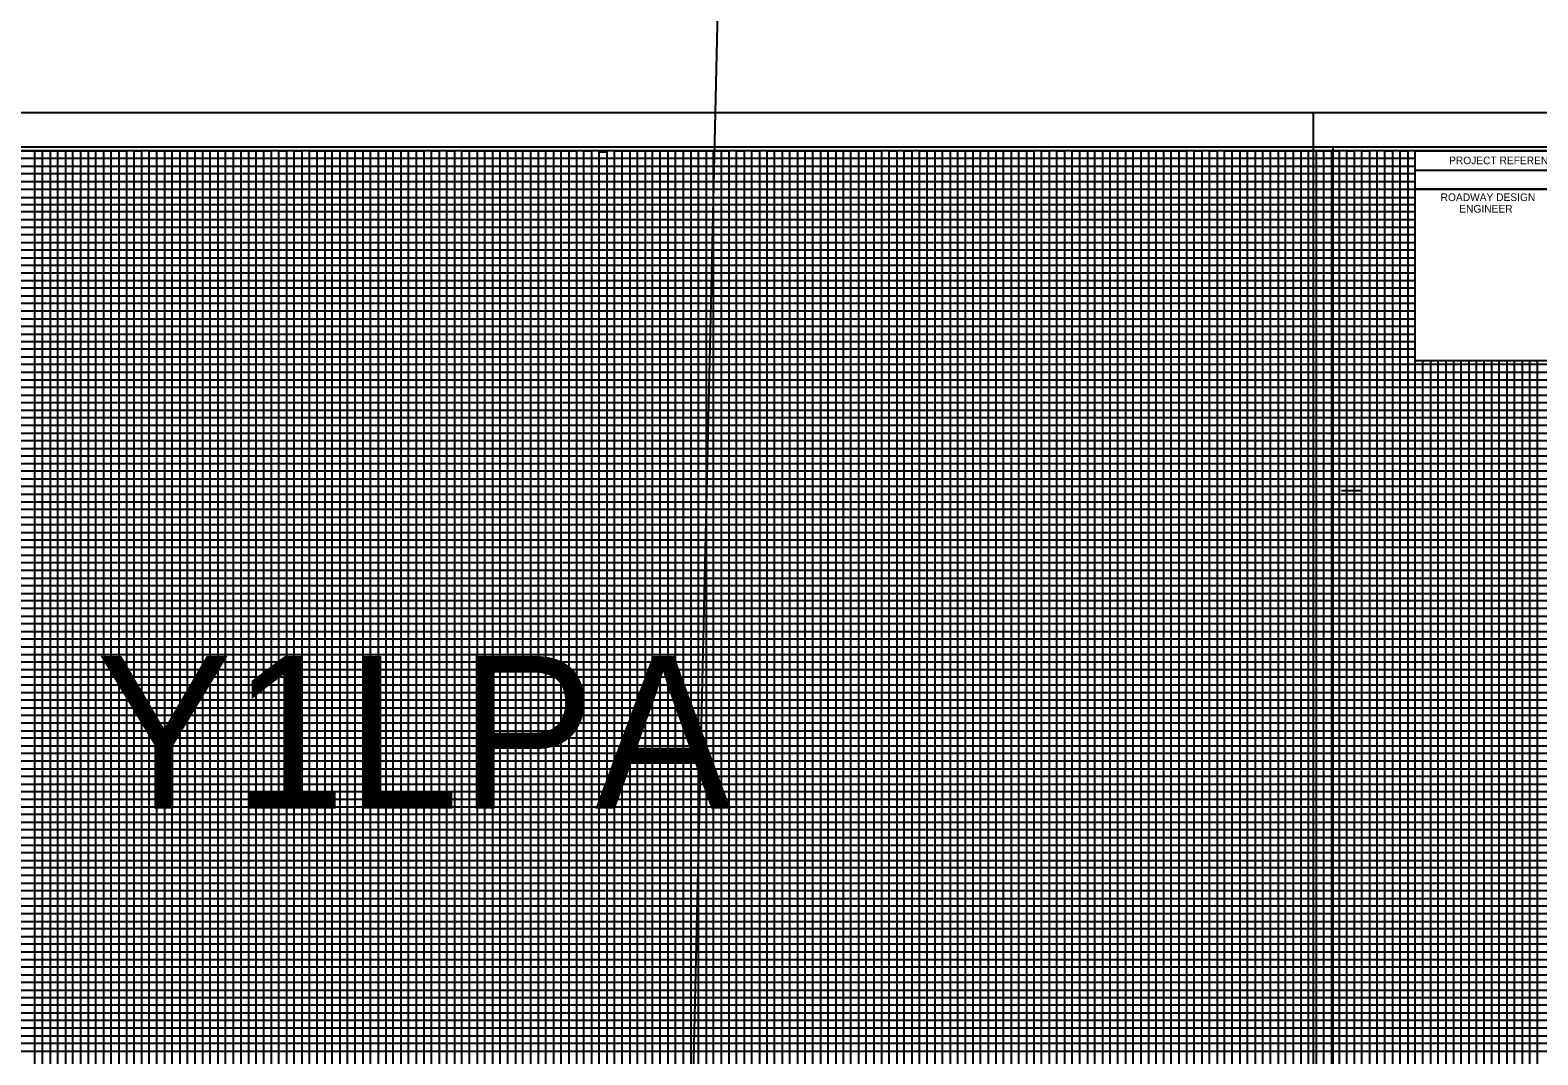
# Model space of a CAD drawing. Extents: x 2345490 to 2436403, y 465165 to 573888.
# Drawn here: x 2411237 to 2412226, y 518915 to 519587 of the extents above; entities that cross this region are included whole.
import ezdxf

# ---------------------------------------------------------------- set-up
doc = ezdxf.new("R2010")
doc.units = 0
for name, color, linetype in [('Old_Level_18', 7, 'Continuous'), ('Old_Level_2', 7, 'Continuous'), ('Old_Level_3', 7, 'Continuous'), ('Old_Level_40', 7, 'Continuous'), ('Old_Level_41', 7, 'Continuous'), ('Old_Level_42', 7, 'Continuous'), ('Old_Level_43', 7, 'Continuous'), ('Old_Level_44', 7, 'Continuous'), ('Old_Level_50', 7, 'Continuous'), ('Old_Level_51', 7, 'Continuous')]:
    doc.layers.add(name, color=color, linetype=linetype)

msp = doc.modelspace()

# ---------------------------------------------------------------- linework, layer by layer
at = {"layer": 'Old_Level_18'}
msp.add_lwpolyline([(2412345.325, 519507.40475), (2410845.325, 519507.40475), (2410845.325, 518457.40475), (2412345.325, 518457.40475)], close=True, dxfattribs=at)
at = {"layer": 'Old_Level_2'}
msp.add_line((2411722.59175, 521117.51825), (2411239.1575, 499960.77), dxfattribs=at)
at = {"layer": 'Old_Level_40'}
msp.add_line((2412145.275, 519494.85475), (2412345.325, 519494.85475), dxfattribs=at)
for points in [[(2412145.275, 519507.40475), (2412345.325, 519507.40475), (2412345.325, 519482.35475), (2412145.275, 519482.35475)], [(2412145.275, 519482.35475), (2412245.325, 519482.35475), (2412245.325, 519369.85475), (2412145.275, 519369.85475)]]:
    msp.add_lwpolyline(points, close=True, dxfattribs=at)
at = {"layer": 'Old_Level_41'}
msp.add_line((2412096.825, 519284.90475), (2412109.325, 519284.90475), dxfattribs=at)
for points in [[(2411220.325, 519507.40475), (2411270.325, 519507.40475), (2411270.325, 518482.40475)], [(2411245.325, 518482.40475), (2411245.325, 519507.40475), (2411295.325, 519507.40475), (2411295.325, 518482.40475)], [(2411320.325, 518482.40475), (2411320.325, 519507.40475), (2411370.325, 519507.40475), (2411370.325, 518482.40475)], [(2411345.325, 518482.40475), (2411345.325, 519507.40475), (2411395.325, 519507.40475), (2411395.325, 518482.40475)], [(2411420.325, 518482.40475), (2411420.325, 519507.40475), (2411470.325, 519507.40475), (2411470.325, 518482.40475)], [(2411445.325, 518482.40475), (2411445.325, 519507.40475), (2411495.325, 519507.40475), (2411495.325, 518482.40475)], [(2411520.325, 518482.40475), (2411520.325, 519507.40475), (2411570.325, 519507.40475), (2411570.325, 518482.40475)], [(2411545.325, 518482.40475), (2411545.325, 519507.40475), (2411595.325, 519507.40475), (2411595.325, 518482.40475)], [(2411620.325, 518482.40475), (2411620.325, 519507.40475), (2411670.325, 519507.40475), (2411670.325, 518482.40475)], [(2411645.325, 518482.40475), (2411645.325, 519507.40475), (2411695.325, 519507.40475), (2411695.325, 518482.40475)], [(2411720.325, 518482.40475), (2411720.325, 519507.40475), (2411770.325, 519507.40475), (2411770.325, 518482.40475)], [(2411745.325, 518482.40475), (2411745.325, 519507.40475), (2411795.325, 519507.40475), (2411795.325, 518482.40475)], [(2411820.325, 518482.40475), (2411820.325, 519507.40475), (2411870.325, 519507.40475), (2411870.325, 518482.40475)], [(2411845.325, 518482.40475), (2411845.325, 519507.40475), (2411895.325, 519507.40475), (2411895.325, 518482.40475)], [(2411920.325, 518482.40475), (2411920.325, 519507.40475), (2411970.325, 519507.40475), (2411970.325, 518482.40475)], [(2411945.325, 518482.40475), (2411945.325, 519507.40475), (2411995.325, 519507.40475), (2411995.325, 518482.40475)], [(2412020.325, 518482.40475), (2412020.325, 519507.40475), (2412070.325, 519507.40475), (2412070.325, 518482.40475)], [(2412045.325, 518482.40475), (2412045.325, 519507.40475), (2412095.325, 519507.40475), (2412095.325, 518482.40475)], [(2412120.325, 518482.40475), (2412120.325, 519507.40475)], [(2412145.325, 518482.40475), (2412145.325, 519507.40475), (2412171.625, 519507.40475)], [(2410845.325, 519457.40475), (2412145.275, 519457.40475)], [(2412145.275, 519407.40475), (2410845.325, 519407.40475), (2410845.325, 519357.35475), (2412345.325, 519357.35475)], [(2412345.325, 519332.40475), (2410845.325, 519332.40475), (2410845.325, 519382.40475), (2412145.275, 519382.40475)], [(2412170.325, 519369.85475), (2412170.325, 518482.40475), (2412220.325, 518482.40475), (2412220.325, 519369.85475)], [(2412345.325, 519307.40475), (2410845.325, 519307.40475), (2410845.325, 519257.40475), (2412345.325, 519257.40475)], [(2412345.325, 519232.40475), (2410845.325, 519232.40475), (2410845.325, 519282.40475), (2412345.325, 519282.40475)], [(2412345.325, 519207.40475), (2410845.325, 519207.40475), (2410845.325, 519157.40475), (2412345.325, 519157.40475)], [(2412345.325, 519107.40475), (2410845.325, 519107.40475), (2410845.325, 519057.40475), (2412345.325, 519057.40475)], [(2412345.325, 519007.40475), (2410845.325, 519007.40475), (2410845.325, 518957.40475), (2412345.325, 518957.40475)]]:
    msp.add_lwpolyline(points, dxfattribs=at)
at = {"layer": 'Old_Level_42'}
for points in [[(2412145.275, 519432.40475), (2410845.425, 519432.40475), (2410845.425, 519482.35475), (2412145.275, 519482.35475)], [(2412195.325, 519369.85475), (2412195.325, 518482.40475), (2412245.325, 518482.40475), (2412245.325, 519369.85475)], [(2412345.325, 519132.40475), (2410845.325, 519132.40475), (2410845.325, 519182.40475), (2412345.325, 519182.40475)], [(2412345.325, 519032.40475), (2410845.325, 519032.40475), (2410845.325, 519082.40475), (2412345.325, 519082.40475)], [(2412345.325, 518932.40475), (2410845.325, 518932.40475), (2410845.325, 518982.40475), (2412345.325, 518982.40475)]]:
    msp.add_lwpolyline(points, dxfattribs=at)
at = {"layer": 'Old_Level_43'}
for p, q in [((2412295.325, 519327.40475), (2410895.325, 519327.40475)), ((2410895.325, 519322.40475), (2412295.325, 519322.40475)), ((2412295.325, 519302.40475), (2410895.325, 519302.40475))]:
    msp.add_line(p, q, dxfattribs=at)
for points in [[(2412145.275, 519502.40475), (2410895.325, 519502.40475), (2410895.325, 519497.40475), (2412145.275, 519497.40475)], [(2411240.325, 518482.40475), (2411240.325, 519507.40475), (2411250.325, 519507.40475), (2411250.325, 518482.40475)], [(2411255.325, 518482.40475), (2411255.325, 519507.40475), (2411260.325, 519507.40475), (2411260.325, 518482.40475)], [(2411265.325, 518482.40475), (2411265.325, 519507.40475), (2411275.325, 519507.40475), (2411275.325, 518482.40475)], [(2411280.325, 518482.40475), (2411280.325, 519507.40475), (2411285.325, 519507.40475), (2411285.325, 518482.40475)], [(2411290.325, 518482.40475), (2411290.325, 519507.40475), (2411300.325, 519507.40475), (2411300.325, 518482.40475)], [(2411305.325, 518482.40475), (2411305.325, 519507.40475), (2411310.325, 519507.40475), (2411310.325, 518482.40475)], [(2411315.325, 518482.40475), (2411315.325, 519507.40475), (2411325.325, 519507.40475), (2411325.325, 518482.40475)], [(2411330.325, 518482.40475), (2411330.325, 519507.40475), (2411335.325, 519507.40475), (2411335.325, 518482.40475)], [(2411340.325, 518482.40475), (2411340.325, 519507.40475), (2411350.325, 519507.40475), (2411350.325, 518482.40475)], [(2411355.325, 518482.40475), (2411355.325, 519507.40475), (2411360.325, 519507.40475), (2411360.325, 518482.40475)], [(2411365.325, 518482.40475), (2411365.325, 519507.40475), (2411375.325, 519507.40475), (2411375.325, 518482.40475)], [(2411380.325, 519507.40475), (2411380.325, 518482.40475), (2411385.325, 518482.40475), (2411385.325, 519507.40475), (2411390.325, 519507.40475), (2411390.325, 518482.40475), (2411400.325, 518482.40475), (2411400.325, 519507.40475), (2411405.325, 519507.40475), (2411405.325, 518482.40475), (2411410.325, 518482.40475), (2411410.325, 519507.40475), (2411415.325, 519507.40475), (2411415.325, 518482.40475)], [(2411425.325, 518482.40475), (2411425.325, 519507.40475), (2411430.325, 519507.40475), (2411430.325, 518482.40475)], [(2411435.325, 518482.40475), (2411435.325, 519507.40475), (2411440.325, 519507.40475), (2411440.325, 518482.40475)], [(2411450.325, 518482.40475), (2411450.325, 519507.40475), (2411455.325, 519507.40475), (2411455.325, 518482.40475)], [(2411460.325, 518482.40475), (2411460.325, 519507.40475), (2411465.325, 519507.40475), (2411465.325, 518482.40475)], [(2411475.325, 518482.40475), (2411475.325, 519507.40475), (2411480.325, 519507.40475), (2411480.325, 518482.40475)], [(2411485.325, 518482.40475), (2411485.325, 519507.40475), (2411490.325, 519507.40475), (2411490.325, 518482.40475)], [(2411500.325, 518482.40475), (2411500.325, 519507.40475), (2411505.325, 519507.40475), (2411505.325, 518482.40475)], [(2411510.325, 518482.40475), (2411510.325, 519507.40475), (2411515.325, 519507.40475), (2411515.325, 518482.40475)], [(2411525.325, 518482.40475), (2411525.325, 519507.40475), (2411530.325, 519507.40475), (2411530.325, 518482.40475)], [(2411535.325, 518482.40475), (2411535.325, 519507.40475), (2411540.325, 519507.40475), (2411540.325, 518482.40475)], [(2411550.325, 518482.40475), (2411550.325, 519507.40475), (2411555.325, 519507.40475), (2411555.325, 518482.40475)], [(2411560.325, 518482.40475), (2411560.325, 519507.40475), (2411565.325, 519507.40475), (2411565.325, 518482.40475)], [(2411575.325, 518482.40475), (2411575.325, 519507.40475), (2411580.325, 519507.40475), (2411580.325, 518482.40475)], [(2411585.325, 518482.40475), (2411585.325, 519507.40475), (2411590.325, 519507.40475), (2411590.325, 518482.40475)], [(2411600.325, 518482.40475), (2411600.325, 519507.40475), (2411605.325, 519507.40475), (2411605.325, 518482.40475)], [(2411610.325, 518482.40475), (2411610.325, 519506.80475), (2411615.325, 519506.80475), (2411615.325, 518482.40475)], [(2411625.325, 518482.40475), (2411625.325, 519507.40475), (2411630.325, 519507.40475), (2411630.325, 518482.40475)], [(2411635.325, 518482.40475), (2411635.325, 519507.40475), (2411640.325, 519507.40475), (2411640.325, 518482.40475)], [(2411650.325, 518482.40475), (2411650.325, 519507.40475), (2411655.325, 519507.40475), (2411655.325, 518482.40475)], [(2411660.325, 518482.40475), (2411660.325, 519507.40475), (2411665.325, 519507.40475), (2411665.325, 518482.40475)], [(2411675.325, 518482.40475), (2411675.325, 519507.40475), (2411680.325, 519507.40475), (2411680.325, 518482.40475)], [(2411685.325, 518482.40475), (2411685.325, 519507.40475), (2411690.325, 519507.40475), (2411690.325, 518482.40475)], [(2411700.325, 518482.40475), (2411700.325, 519507.40475), (2411705.325, 519507.40475), (2411705.325, 518482.40475)], [(2411710.325, 518482.40475), (2411710.325, 519507.40475), (2411715.325, 519507.40475), (2411715.325, 518482.40475)], [(2411725.325, 518482.40475), (2411725.325, 519507.40475), (2411730.325, 519507.40475), (2411730.325, 518482.40475)], [(2411735.325, 518482.40475), (2411735.325, 519507.40475), (2411740.325, 519507.40475), (2411740.325, 518482.40475)], [(2411750.325, 518482.40475), (2411750.325, 519507.40475), (2411755.325, 519507.40475), (2411755.325, 518482.40475)], [(2411760.325, 518482.40475), (2411760.325, 519507.40475), (2411765.325, 519507.40475), (2411765.325, 518482.40475)], [(2411775.325, 518482.40475), (2411775.325, 519507.40475), (2411780.325, 519507.40475), (2411780.325, 518482.40475)], [(2411785.325, 518482.40475), (2411785.325, 519507.40475), (2411790.325, 519507.40475), (2411790.325, 518482.40475)], [(2411800.325, 518482.40475), (2411800.325, 519507.40475), (2411805.325, 519507.40475), (2411805.325, 518482.40475)], [(2411810.325, 518482.40475), (2411810.325, 519507.40475), (2411815.325, 519507.40475), (2411815.325, 518482.40475)], [(2411825.325, 518482.40475), (2411825.325, 519507.40475), (2411830.325, 519507.40475), (2411830.325, 518482.40475)], [(2411835.325, 518482.40475), (2411835.325, 519507.40475), (2411840.325, 519507.40475), (2411840.325, 518482.40475)], [(2411850.325, 518482.40475), (2411850.325, 519507.40475), (2411855.325, 519507.40475), (2411855.325, 518482.40475)], [(2411860.325, 518482.40475), (2411860.325, 519507.40475), (2411865.325, 519507.40475), (2411865.325, 518482.40475)], [(2411875.325, 518482.40475), (2411875.325, 519507.40475), (2411880.325, 519507.40475), (2411880.325, 518482.40475)], [(2411885.325, 518482.40475), (2411885.325, 519507.40475), (2411890.325, 519507.40475), (2411890.325, 518482.40475)], [(2411900.325, 518482.40475), (2411900.325, 519507.40475), (2411905.325, 519507.40475), (2411905.325, 518482.40475)], [(2411910.325, 518482.40475), (2411910.325, 519507.40475), (2411915.325, 519507.40475), (2411915.325, 518482.40475)], [(2411925.325, 518482.40475), (2411925.325, 519507.40475), (2411930.325, 519507.40475), (2411930.325, 518482.40475)], [(2411935.325, 518482.40475), (2411935.325, 519507.40475), (2411940.325, 519507.40475), (2411940.325, 518482.40475)], [(2411950.325, 518482.40475), (2411950.325, 519507.40475), (2411955.325, 519507.40475), (2411955.325, 518482.40475)], [(2411960.325, 518482.40475), (2411960.325, 519507.40475), (2411965.325, 519507.40475), (2411965.325, 518482.40475)], [(2411975.325, 518482.40475), (2411975.325, 519507.40475), (2411980.325, 519507.40475), (2411980.325, 518482.40475)], [(2411985.325, 518482.40475), (2411985.325, 519507.40475), (2411990.325, 519507.40475), (2411990.325, 518482.40475)], [(2412000.325, 518482.40475), (2412000.325, 519507.40475), (2412005.325, 519507.40475), (2412005.325, 518482.40475)], [(2412010.325, 518482.40475), (2412010.325, 519507.40475), (2412015.325, 519507.40475), (2412015.325, 518482.40475)], [(2412025.325, 518482.40475), (2412025.325, 519507.40475), (2412030.325, 519507.40475), (2412030.325, 518482.40475)], [(2412035.325, 518482.40475), (2412035.325, 519507.40475), (2412040.325, 519507.40475), (2412040.325, 518482.40475)], [(2412050.325, 518482.40475), (2412050.325, 519507.40475), (2412055.325, 519507.40475), (2412055.325, 518482.40475)], [(2412060.325, 518482.40475), (2412060.325, 519507.40475), (2412065.325, 519507.40475), (2412065.325, 518482.40475)], [(2412075.325, 518482.40475), (2412075.325, 519507.40475), (2412080.325, 519507.40475), (2412080.325, 518482.40475)], [(2412085.325, 518482.40475), (2412085.325, 519507.40475), (2412090.325, 519507.40475), (2412090.325, 518482.40475)], [(2412100.325, 518482.40475), (2412100.325, 519507.40475), (2412105.325, 519507.40475), (2412105.325, 518482.40475)], [(2412110.325, 518482.40475), (2412110.325, 519507.40475), (2412115.325, 519507.40475), (2412115.325, 518482.40475)], [(2412125.325, 518482.40475), (2412125.325, 519507.40475), (2412130.325, 519507.40475), (2412130.325, 518482.40475)], [(2412135.325, 518482.40475), (2412135.325, 519507.40475), (2412140.325, 519507.40475), (2412140.325, 518482.40475)], [(2412145.275, 519492.40475), (2410895.325, 519492.40475), (2410895.325, 519487.40475), (2412145.275, 519487.40475)], [(2412145.275, 519476.65475), (2410896.325, 519476.65475), (2410896.325, 519472.40475), (2412145.275, 519472.40475)], [(2412145.275, 519467.40475), (2410895.325, 519467.40475), (2410895.325, 519462.40475), (2412145.275, 519462.40475)], [(2412145.275, 519452.40475), (2410895.325, 519452.40475), (2410895.325, 519447.40475), (2412145.275, 519447.40475)], [(2412145.275, 519442.40475), (2410895.325, 519442.40475), (2410895.325, 519437.40475), (2412145.275, 519437.40475)], [(2412145.275, 519427.40475), (2410895.325, 519427.40475), (2410895.325, 519422.40475), (2412145.275, 519422.40475)], [(2412145.275, 519417.40475), (2410895.325, 519417.40475), (2410895.325, 519412.40475), (2412145.275, 519412.40475)], [(2412145.275, 519402.40475), (2410895.325, 519402.40475), (2410895.325, 519397.40475), (2412145.275, 519397.40475)], [(2412145.275, 519392.40475), (2410895.325, 519392.40475), (2410895.325, 519387.40475), (2412145.275, 519387.40475)], [(2412145.275, 519377.40475), (2410895.325, 519377.40475), (2410895.325, 519372.40475), (2412145.275, 519372.40475)], [(2412150.325, 518482.40475), (2412150.325, 519369.85475)], [(2412155.325, 519369.85475), (2412155.325, 518482.40475), (2412160.325, 518482.40475), (2412160.325, 519369.85475)], [(2412165.325, 519369.85475), (2412165.325, 518482.40475), (2412175.325, 518482.40475), (2412175.325, 519369.85475)], [(2412180.325, 519369.85475), (2412180.325, 518482.40475), (2412185.325, 518482.40475), (2412185.325, 519369.85475)], [(2412190.325, 519369.85475), (2412190.325, 518482.40475), (2412200.325, 518482.40475), (2412200.325, 519369.85475)], [(2412205.325, 519369.85475), (2412205.325, 518482.40475), (2412210.325, 518482.40475), (2412210.325, 519369.85475)], [(2412215.325, 519369.85475), (2412215.325, 518482.40475), (2412225.325, 518482.40475), (2412225.325, 519369.85475)], [(2412295.325, 519367.40475), (2410895.325, 519367.40475), (2410895.325, 519367.40475), (2410895.325, 519347.40475), (2412295.325, 519347.40475)], [(2410895.325, 519362.40475), (2412295.325, 519362.40475)], [(2412295.325, 519352.40475), (2410895.325, 519352.40475)], [(2412295.325, 519342.40475), (2410895.325, 519342.40475), (2410895.325, 519337.40475), (2412295.325, 519337.40475)], [(2412295.325, 519317.40475), (2410895.325, 519317.40475), (2410895.325, 519312.40475), (2412295.325, 519312.40475)], [(2412295.325, 519297.40475), (2410895.325, 519297.40475), (2410895.325, 519292.40475), (2412295.325, 519292.40475)], [(2412295.325, 519287.40475), (2410895.325, 519287.40475)], [(2410895.325, 519277.40475), (2412295.325, 519277.40475)], [(2412295.325, 519272.40475), (2410895.325, 519272.40475), (2410895.325, 519267.40475), (2412295.325, 519267.40475)], [(2412295.325, 519262.40475), (2410895.325, 519262.40475), (2410895.325, 519252.40475), (2412295.325, 519252.40475)], [(2412295.325, 519247.40475), (2410895.325, 519247.40475), (2410895.325, 519242.40475), (2412295.325, 519242.40475)], [(2412295.325, 519237.40475), (2410895.325, 519237.40475), (2410895.325, 519227.40475), (2412295.325, 519227.40475)], [(2412295.325, 519222.40475), (2410895.325, 519222.40475), (2410895.325, 519217.40475), (2412295.325, 519217.40475)], [(2412295.325, 519212.40475), (2410895.325, 519212.40475), (2410895.325, 519202.40475), (2412295.325, 519202.40475)], [(2412295.325, 519197.40475), (2410895.325, 519197.40475), (2410895.325, 519192.40475), (2412295.325, 519192.40475)], [(2412295.325, 519187.40475), (2410895.325, 519187.40475), (2410895.325, 519177.40475), (2412295.325, 519177.40475)], [(2412295.325, 519172.40475), (2410895.325, 519172.40475), (2410895.325, 519167.40475), (2412295.325, 519167.40475)], [(2412295.325, 519162.40475), (2410895.325, 519162.40475), (2410895.325, 519152.40475), (2412295.325, 519152.40475)], [(2412295.325, 519147.40475), (2410895.325, 519147.40475), (2410895.325, 519142.40475), (2412295.325, 519142.40475)], [(2412295.325, 519137.40475), (2410895.325, 519137.40475), (2410895.325, 519127.40475), (2412295.325, 519127.40475)], [(2412295.325, 519122.40475), (2410895.325, 519122.40475), (2410895.325, 519117.40475), (2412295.325, 519117.40475)], [(2412295.325, 519112.40475), (2410895.325, 519112.40475), (2410895.325, 519102.40475), (2412295.325, 519102.40475)], [(2412295.325, 519097.40475), (2410895.325, 519097.40475), (2410895.325, 519092.40475), (2412295.325, 519092.40475)], [(2412295.325, 519087.40475), (2410895.325, 519087.40475), (2410895.325, 519077.40475), (2412295.325, 519077.40475)], [(2412295.325, 519072.40475), (2410895.325, 519072.40475), (2410895.325, 519067.40475), (2412295.325, 519067.40475)], [(2412295.325, 519062.40475), (2410895.325, 519062.40475), (2410895.325, 519052.40475), (2412295.325, 519052.40475)], [(2412295.325, 519047.40475), (2410895.325, 519047.40475), (2410895.325, 519042.40475), (2412295.325, 519042.40475)], [(2412295.325, 519037.40475), (2410895.325, 519037.40475), (2410895.325, 519027.40475), (2412295.325, 519027.40475)], [(2412295.325, 519022.40475), (2410895.325, 519022.40475), (2410895.325, 519017.40475), (2412295.325, 519017.40475)], [(2412295.325, 519012.40475), (2410895.325, 519012.40475), (2410895.325, 519002.40475), (2412295.325, 519002.40475)], [(2412295.325, 518997.40475), (2410895.325, 518997.40475), (2410895.325, 518992.40475), (2412295.325, 518992.40475)], [(2412295.325, 518987.40475), (2410895.325, 518987.40475)], [(2410895.325, 518977.40475), (2412295.325, 518977.40475)], [(2412295.325, 518972.40475), (2410895.325, 518972.40475), (2410895.325, 518967.40475), (2412295.325, 518967.40475)], [(2412295.325, 518962.40475), (2410895.325, 518962.40475), (2410895.325, 518952.40475), (2412295.325, 518952.40475)], [(2412295.325, 518947.40475), (2410895.325, 518947.40475), (2410895.325, 518942.40475), (2412295.325, 518942.40475)], [(2412295.325, 518937.40475), (2410895.325, 518937.40475), (2410895.325, 518927.40475), (2412295.325, 518927.40475)], [(2412295.325, 518922.40475), (2410895.325, 518922.40475), (2410895.325, 518917.40475), (2412295.325, 518917.40475)]]:
    msp.add_lwpolyline(points, dxfattribs=at)
at = {"layer": 'Old_Level_50'}
for points in [[(2412357.825, 519509.95475), (2410691.325, 519509.95475), (2410691.325, 518454.85475), (2412357.825, 518454.85475)], [(2413757.825, 519509.95475), (2412091.325, 519509.95475), (2412091.325, 518454.85475), (2413757.825, 518454.85475)]]:
    msp.add_lwpolyline(points, close=True, dxfattribs=at)
at = {"layer": 'Old_Level_51'}
for points in [[(2412362.325, 519532.40475), (2410678.325, 519532.40475), (2410678.325, 518432.40475), (2412362.325, 518432.40475)], [(2413762.325, 519532.40475), (2412078.325, 519532.40475), (2412078.325, 518432.40475), (2413762.325, 518432.40475)]]:
    msp.add_lwpolyline(points, close=True, dxfattribs=at)

# ---------------------------------------------------------------- texts
at = {"layer": 'Old_Level_3'}
msp.add_text('Y1LPA', height=99.999999, dxfattribs=at).set_placement((2411280.4125, 519076.36175))
at = {"layer": 'Old_Level_44'}
for s, p in [('PROJECT REFERENCE NO.', (2412167.475, 519498.70475)), ('ROADWAY DESIGN', (2412161.925, 519474.60475)), ('ENGINEER', (2412174.175, 519467.00475))]:
    msp.add_text(s, height=5.0001, dxfattribs=at).set_placement(p)

doc.saveas('drawing.dxf')
